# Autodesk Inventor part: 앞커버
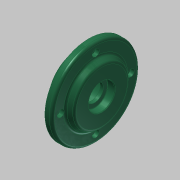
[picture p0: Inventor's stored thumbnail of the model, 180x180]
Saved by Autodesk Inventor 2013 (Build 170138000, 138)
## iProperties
Created: 2015-11
Part Number: 앞커버
Material: 일반
Document SubType Name: Modeling
Designer: mduedu
Density: 2.71 g/cm^3
Author: mduedu
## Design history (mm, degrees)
sketch "스케치1"
  geometry: C1 r 50 at (0, 0); 1 further point
  constraints: 1 centre point, 1 coincident
  dimensions: "d57" = 100 diameter of C1
extrude "돌출1" new body sketch "스케치1" distance "d3" = 8; taper "d4" = 0 deg
sketch "스케치2"
  geometry: C1 r 35 at (0, 0); 1 further point
  constraints: 1 centre point, 1 coincident
  dimensions: "d5" = 70 diameter of C1
extrude "돌출2" join sketch "스케치2" distance "d6" = 7; taper "d7" = -30 deg
sketch "스케치3" dims "d58" = 80
  geometry: 3 further points
  constraints: 2 vertical alignment, 1 coincident, 2 other
hole "구멍1" sketch "스케치3" at (0, 40) diameter "d11" = 4.5; stored, may be unused: countersink angle "d15" = 90 deg, drill point angle "d17" = 118 deg; dims "d12" = 6, "d13" = 8, "d14" = 4.4, "d16" = 8
sketch "스케치4"
  geometry: C1 r 35 at (0, 0); 1 further point
  constraints: 1 centre point, 1 coincident
  dimensions: "d21" = 70 diameter of C1
extrude "돌출3" join sketch "스케치4" distance "d23" = 12; taper "d24" = 0 deg
hole "구멍2" diameter "d27" = 30; stored, may be unused: countersink angle "d31" = 90 deg, drill point angle "d33" = 0 deg; dims "d25" = 10, "d26" = 10, "d28" = 6, "d29" = 40, "d30" = 12, "d32" = 15
fillet "모깎기3" dims "d36" = 3
fillet "모깎기4" dims "d37" = 3
fillet "모깎기5" dims "d38" = 0.3
chamfer "모따기1" distance "d39" = 1; stored, may be unused: second distance "d40" = 2, angle "d41" = 45 deg
hole "구멍3" diameter "d44" = 20; stored, may be unused: countersink angle "d48" = 90 deg, drill point angle "d50" = 118 deg; dims "d45" = 6, "d46" = 30, "d47" = 8.3, "d49" = 8, "d59" = 10, "d60" = 10
fillet "모깎기6" dims "d51" = 0.3
chamfer "모따기2" distance "d52" = 0.8; stored, may be unused: second distance "d53" = 2, angle "d54" = 30 deg
node "솔리드1"
pattern_circular "원형 패턴1" dims angle "d19" = 360 deg
